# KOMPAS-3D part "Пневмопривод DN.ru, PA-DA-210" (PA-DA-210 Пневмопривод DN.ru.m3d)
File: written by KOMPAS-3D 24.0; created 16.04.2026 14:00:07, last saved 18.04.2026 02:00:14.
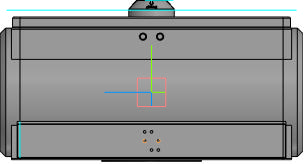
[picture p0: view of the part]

Document properties: Автор: DN.ru; Полное имя файла: C:\Работа\PA-DA-х Пневмопривод DN.ru\210\исходные материалы\PA-DA-210 Пневмопривод DN.ru.m3d

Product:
- Body: Тело 1  | qty 1
    Масса: 206.114249
- Body: Тело 2  | qty 1
    Масса: 206.114249
- Part/product: Пневмопривод DN.ru  | designation PA-DA-210
    Масса: 47
    Раздел спецификации: Прочие изделия
    Примечание: D290-00300

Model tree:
1. Эскиз:1
2. Элемент выдавливания:1
3. Эскиз:2  (with: Ребро.Элемент выдавливания:1)
4. Элемент выдавливания:2
5. Эскиз:3  (with: Ребро.Элемент выдавливания:2)
6. Элемент выдавливания:3  (with: Грань.Элемент выдавливания:2)
     Смещение 1 = -2; Расстояние 2 = 244; Смещение 2 = -2
7. Эскиз:4  (with: Грань.Элемент выдавливания:3)
8. Элемент выдавливания:4
9. Эскиз:6  (with: Ребро.Элемент выдавливания:2)
10. Элемент выдавливания:6
11. Отверстие:2  (with: Грань.Элемент выдавливания:6)
     Глубина выреза = 10; Диаметр отверстия = 5; Угол конуса дна = 120; Расстояние 2 = 14
12. Массив по сетке:2  (with: Отверстие:2)  (3 pattern instances)
     Шаг 1 = 12; Угол раствора = 90; Шаг 2 = 32
13. Массив по сетке:3  (with: Отверстие:2)  (2 pattern instances)
     Шаг 1 = 32; Угол раствора = 90; Шаг 2 = 12
14. Отверстие:3  (with: Грань.Элемент выдавливания:6, Ребро.Элемент выдавливания:6)  (labels: W 1/4'')
     Глубина выреза = 10; Диаметр отверстия = 4.72357; Угол конуса дна = 120; Расстояние 1 = 12; Расстояние 2 = 30
15. W 1/4''  (with: Грань.Отверстие:3, Грань.Элемент выдавливания:6)  (labels: cil5_ex_DIN 477 BSW coarse)
     Длина резьбы = 8; Шаг резьбы = 1.27; Номинальный диаметр резьбы = 6.35
16. Массив по сетке:4  (with: Отверстие:3)  (labels: W 1/4'')  (2 pattern instances)
17. Эскиз:7  (with: Грань.Элемент выдавливания:2)
18. Элемент выдавливания:7
19. Эскиз:8  (with: Грань.Элемент выдавливания:2, Ребро.Элемент выдавливания:2)
20. Элемент выдавливания:8  (with: Грань.Элемент выдавливания:6)
     Расстояние 2 = 4
21. Отверстие:4  (with: Грань.Элемент выдавливания:2)
     Глубина выреза = 7; Диаметр отверстия = 10; Угол конуса дна = 118; Расстояние 1 = 15; Расстояние 2 = 15; Диаметр зенковки = 13.2; Глубина зенковки = 1.6; Угол зенковки = 90
22. Массив по сетке:5  (with: Отверстие:4)  (2 pattern instances)
     Шаг 1 = 30; Угол раствора = 90
23. Отверстие:5  (with: Грань.Элемент выдавливания:3)
     Глубина выреза = 10; Диаметр отверстия = 5; Угол конуса дна = 120; Диаметр зенковки = 7; Глубина зенковки = 1; Угол зенковки = 90
24. Массив по сетке:6  (with: Отверстие:5)  (4 pattern instances)
     Угол раствора = 90
25. Фаска:1  (with: Ребро.Элемент выдавливания:4)
     Угол = 45; Длина 1 = 15; Длина 2 = 15
26. Скругление:2  (with: Ребро.Элемент выдавливания:3)
     Радиус = 2
27. Скругление:3  (with: Ребро.Элемент выдавливания:6)
     Радиус = 3
28. Скругление:4  (with: Ребро.Элемент выдавливания:8, Ребро.Элемент выдавливания:2)
     Радиус = 2
29. Скругление:5  (with: Ребро.Элемент выдавливания:6)
     Радиус = 1
30. Смещенная плоскость:1  (with: Грань.Элемент выдавливания:3)
31. Эскиз:9
32. Элемент выдавливания:9  (with: Грань.Фаска:1)
     Расстояние 1 = 43.4142; Смещение 1 = 1
33. Смещенная плоскость:2  (with: Грань.Элемент выдавливания:4)
     Расстояние = 0.5
34. Эскиз:10
35. Элемент выдавливания:10
     Расстояние 1 = 25.9142
36. Эскиз:11  (with: Грань.Элемент выдавливания:4)
37. Элемент выдавливания:11
     Расстояние 1 = 1
38. Эскиз:12  (with: Грань.Элемент выдавливания:11, Ребро.Элемент выдавливания:11)
39. Элемент выдавливания:12  (with: Грань.Элемент выдавливания:4)
     Расстояние 2 = 1
40. Эскиз:13  (with: Грань.Элемент выдавливания:11)
41. Элемент выдавливания:13  (with: Грань.Элемент выдавливания:4)
     Расстояние 2 = 1
42. Скругление:7  (with: Ребро.Элемент выдавливания:11)
     Радиус = 1
43. Скругление:8  (with: Ребро.Элемент выдавливания:8)
     Радиус = 2
44. Эскиз:14  (with: Грань.Элемент выдавливания:3)
45. Элемент выдавливания:14  (with: Грань.Фаска:1)
     Расстояние 1 = 54.1414; Смещение 1 = 0.1
46. Эскиз:15  (with: Грань.Элемент выдавливания:3, Ребро.Скругление:2)
47. Элемент выдавливания:15
     Расстояние 2 = 0.1
48. Отверстие:6  (with: Грань.Элемент выдавливания:2, Ребро.Элемент выдавливания:2)
     Глубина выреза = 10; Диаметр отверстия = 10; Угол конуса дна = 118; Расстояние 1 = 15; Расстояние 2 = 15; Диаметр цековки = 20; Глубина цековки = 5
49. Зеркальный массив:1
50. Экземпляр ( 1 )
51. Экземпляр ( 2 )  (with: Отверстие:6)
52. Зеркальный массив:2  (with: Экземпляр ( 1 ), Экземпляр ( 2 ), Отверстие:6)
53. Зеркальный массив:3  (with: Экземпляр ( 1 ), Экземпляр ( 2 ), Зеркальный массив:2, Отверстие:6)
54. Зеркальный массив:4  (with: Экземпляр ( 1 ), Экземпляр ( 2 ), Зеркальный массив:1, Отверстие:6, Зеркальный массив:3, Зеркальный массив:2)
55. Фаска:2  (with: Ребро.Элемент выдавливания:7)
     Угол = 45; Длина 1 = 2; Длина 2 = 2
56. Фаска:3  (with: Ребро.Элемент выдавливания:1)
     Угол = 45; Длина 1 = 10; Длина 2 = 10
57. Смещенная плоскость:3  (with: Грань.Элемент выдавливания:6)
     Расстояние = 5
58. Эскиз:16
59. Элемент выдавливания:16
     Расстояние 2 = 0.1
60. Зеркальный массив:5  (with: Экземпляр ( 1 ), Экземпляр ( 2 ), Элемент выдавливания:16)

Expressions: H/2; -G/2; v2053*2; (E-D-6)/2
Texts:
  PA-DA-210
  GOST 26.020 Pr3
